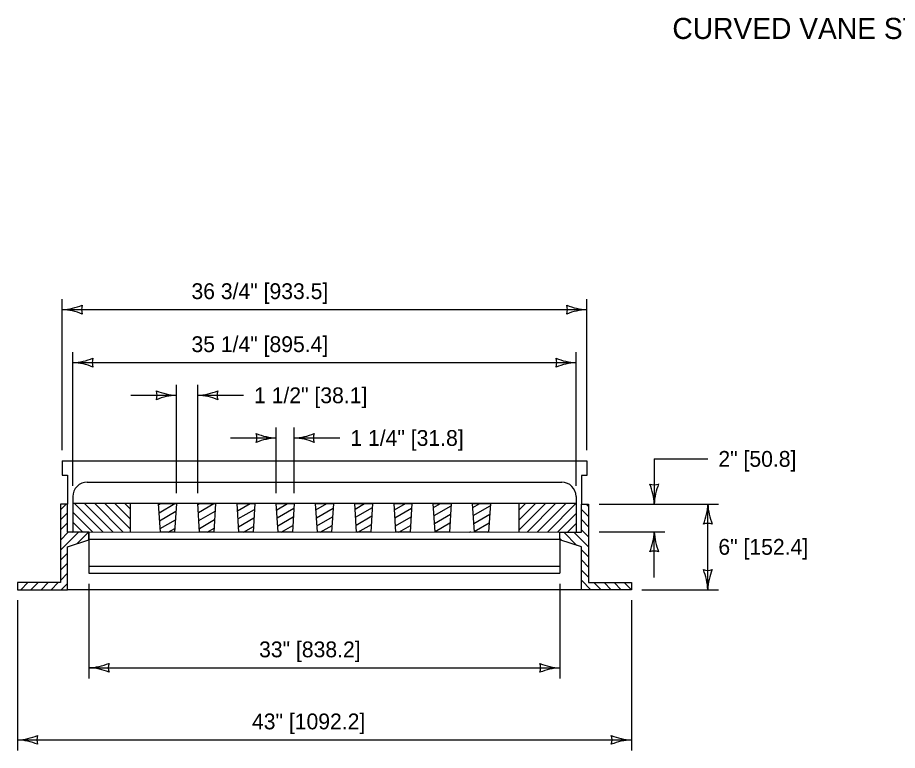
# Model space of a CAD drawing. Extents: x 49991.4 to 50057, y 49987.6 to 50011.4.
# Drawn here: x 50008.587 to 50011.925, y 49993.335 to 49996.116 of the extents above; entities that cross this region are included whole.
import ezdxf

# ---------------------------------------------------------------- set-up
doc = ezdxf.new("R2010")
doc.units = 0
for name, color, linetype in [('Level 1', 7, 'Continuous'), ('Level 2', 7, 'Continuous'), ('Level 3', 7, 'Continuous')]:
    doc.layers.add(name, color=color, linetype=linetype)

msp = doc.modelspace()

# ---------------------------------------------------------------- linework, layer by layer
at = {"layer": 'Level 1'}
for p, q in [((50008.7559, 49994.434), (50008.7559, 49994.3799)), ((50008.7559, 49994.434), (50010.7465, 49994.434)), ((50010.7465, 49994.434), (50010.7465, 49994.3782)), ((50008.7559, 49994.3799), (50008.7762, 49994.3798)), ((50008.7762, 49994.3798), (50008.7762, 49994.2698)), ((50010.7262, 49994.3782), (50010.7262, 49994.2698)), ((50010.7465, 49994.3782), (50010.7262, 49994.3782)), ((50008.8507, 49994.3527), (50010.6518, 49994.3527)), ((50008.7491, 49994.2482), (50008.7707, 49994.2698)), ((50008.7965, 49994.2985), (50008.7965, 49994.2714)), ((50010.7059, 49994.2714), (50008.7965, 49994.2714)), ((50008.7965, 49994.2714), (50008.7965, 49994.163)), ((50008.8025, 49994.2714), (50008.9109, 49994.163)), ((50008.8408, 49994.2714), (50008.9492, 49994.163)), ((50008.8791, 49994.2714), (50008.9875, 49994.163)), ((50008.9174, 49994.2714), (50009.0132, 49994.1757)), ((50008.9557, 49994.2714), (50009.0132, 49994.214)), ((50008.994, 49994.2714), (50009.0132, 49994.2523)), ((50009.0132, 49994.2714), (50009.0132, 49994.163)), ((50009.1218, 49994.2671), (50009.1293, 49994.2714)), ((50009.1237, 49994.2369), (50009.1834, 49994.2714)), ((50009.2707, 49994.2678), (50009.2769, 49994.2714)), ((50009.2726, 49994.2377), (50009.3311, 49994.2714)), ((50009.4212, 49994.2437), (50009.4692, 49994.2714)), ((50009.5699, 49994.2475), (50009.6114, 49994.2714)), ((50009.7188, 49994.2475), (50009.7604, 49994.2714)), ((50009.8676, 49994.2507), (50009.9035, 49994.2714)), ((50010.0167, 49994.2475), (50010.0583, 49994.2714)), ((50010.1652, 49994.2562), (50010.1915, 49994.2714)), ((50010.3141, 49994.2562), (50010.3405, 49994.2714)), ((50010.4892, 49994.2714), (50010.4892, 49994.1646)), ((50010.4892, 49994.1705), (50010.5902, 49994.2714)), ((50010.4892, 49994.2088), (50010.5519, 49994.2714)), ((50010.4892, 49994.2471), (50010.5136, 49994.2714)), ((50010.5217, 49994.1646), (50010.6285, 49994.2714)), ((50010.56, 49994.1646), (50010.6668, 49994.2714)), ((50010.5983, 49994.1646), (50010.7051, 49994.2714)), ((50010.7059, 49994.2985), (50010.7059, 49994.2714)), ((50010.7059, 49994.2714), (50010.7059, 49994.1646)), ((50010.7439, 49994.2698), (50010.7533, 49994.2604)), ((50008.7491, 49994.2099), (50008.7762, 49994.237)), ((50008.7965, 49994.2391), (50008.8726, 49994.163)), ((50009.1255, 49994.2067), (50009.1874, 49994.2425)), ((50009.2745, 49994.2075), (50009.3364, 49994.2432)), ((50009.423, 49994.2135), (50009.4858, 49994.2497)), ((50009.5718, 49994.2173), (50009.635, 49994.2538)), ((50009.7207, 49994.2173), (50009.7839, 49994.2538)), ((50009.8695, 49994.2205), (50009.9331, 49994.2573)), ((50010.0186, 49994.2173), (50010.0819, 49994.2538)), ((50010.167, 49994.226), (50010.2314, 49994.2632)), ((50010.316, 49994.226), (50010.3804, 49994.2632)), ((50010.7262, 49994.2492), (50010.7533, 49994.2221)), ((50009.1274, 49994.1766), (50009.1854, 49994.21)), ((50009.2763, 49994.1773), (50009.3344, 49994.2108)), ((50009.4249, 49994.1833), (50009.4837, 49994.2173)), ((50009.5736, 49994.1871), (50009.633, 49994.2213)), ((50009.7226, 49994.1871), (50009.7819, 49994.2213)), ((50009.8714, 49994.1903), (50009.9311, 49994.2248)), ((50010.0205, 49994.1871), (50010.0798, 49994.2213)), ((50010.1689, 49994.1959), (50010.2294, 49994.2308)), ((50010.3179, 49994.1959), (50010.3783, 49994.2308)), ((50010.6366, 49994.1646), (50010.7059, 49994.2339)), ((50010.7262, 49994.2109), (50010.7533, 49994.1838)), ((50008.7491, 49994.1716), (50008.7762, 49994.1987)), ((50008.7965, 49994.2008), (50008.8343, 49994.163)), ((50009.1583, 49994.1631), (50009.1833, 49994.1776)), ((50009.3059, 49994.1631), (50009.3323, 49994.1784)), ((50009.4441, 49994.1631), (50009.4817, 49994.1848)), ((50009.5863, 49994.1631), (50009.6309, 49994.1889)), ((50009.7352, 49994.1631), (50009.7799, 49994.1889)), ((50009.8784, 49994.1631), (50009.9291, 49994.1924)), ((50010.0331, 49994.1631), (50010.0778, 49994.1889)), ((50010.1708, 49994.1657), (50010.2273, 49994.1983)), ((50010.3198, 49994.1657), (50010.3763, 49994.1983)), ((50010.6749, 49994.1646), (50010.7059, 49994.1956)), ((50010.7262, 49994.1726), (50010.7533, 49994.1455)), ((50008.7491, 49994.095), (50008.8172, 49994.163)), ((50008.7491, 49994.1333), (50008.7789, 49994.163)), ((50008.7762, 49994.1658), (50008.7789, 49994.163)), ((50008.7965, 49994.163), (50010.7262, 49994.1646)), ((50008.8115, 49994.1191), (50008.8555, 49994.163)), ((50008.8574, 49994.163), (50008.8574, 49994.0073)), ((50008.8574, 49994.136), (50010.6449, 49994.136)), ((50010.3018, 49994.1631), (50010.3066, 49994.1659)), ((50010.3695, 49994.1631), (50010.3743, 49994.1659)), ((50010.6449, 49994.139), (50010.6518, 49994.1321)), ((50010.6449, 49994.136), (50010.6449, 49994.0073)), ((50010.6592, 49994.163), (50010.7092, 49994.113)), ((50010.6975, 49994.163), (50010.7533, 49994.1072)), ((50008.7491, 49994.0567), (50008.7762, 49994.0838)), ((50010.7262, 49994.096), (50010.7533, 49994.0689)), ((50008.7491, 49994.0184), (50008.7762, 49994.0455)), ((50010.7262, 49994.0577), (50010.7533, 49994.0306)), ((50008.7491, 49993.9801), (50008.7762, 49994.0072)), ((50008.8574, 49994.0344), (50010.6449, 49994.0344)), ((50008.8574, 49994.0073), (50010.6449, 49994.0073)), ((50010.7262, 49994.0194), (50010.7533, 49993.9923)), ((50008.5866, 49993.9708), (50008.5877, 49993.9719)), ((50008.5989, 49993.9448), (50008.626, 49993.9719)), ((50008.6372, 49993.9448), (50008.6643, 49993.9719)), ((50008.6755, 49993.9448), (50008.7026, 49993.9719)), ((50008.7138, 49993.9448), (50008.7409, 49993.9719)), ((50008.7521, 49993.9448), (50008.7762, 49993.9689)), ((50010.7262, 49993.9811), (50010.7625, 49993.9448)), ((50010.7737, 49993.9719), (50010.8008, 49993.9448)), ((50010.812, 49993.9719), (50010.8391, 49993.9448)), ((50010.8503, 49993.9719), (50010.8774, 49993.9448)), ((50010.8886, 49993.9719), (50010.9157, 49993.9448)), ((50010.7262, 49993.9448), (50008.7762, 49993.9448))]:
    msp.add_line(p, q, dxfattribs=at)
for points in [[(50008.7491, 49994.2698), (50008.7491, 49993.9719), (50008.5866, 49993.9719), (50008.5866, 49993.9448), (50008.7762, 49993.9448), (50008.7762, 49994.1073), (50008.8574, 49994.1344), (50008.8574, 49994.163), (50008.7762, 49994.163), (50008.7762, 49994.163), (50008.7762, 49994.2698)], [(50009.1283, 49994.1631), (50009.1215, 49994.2714), (50009.1892, 49994.2714), (50009.1824, 49994.1631)], [(50009.2772, 49994.1631), (50009.2705, 49994.2714), (50009.3382, 49994.2714), (50009.3314, 49994.1631)], [(50009.4262, 49994.1631), (50009.4194, 49994.2714), (50009.4871, 49994.2714), (50009.4804, 49994.1631)], [(50009.5751, 49994.1631), (50009.5684, 49994.2714), (50009.6361, 49994.2714), (50009.6293, 49994.1631)], [(50009.7241, 49994.1631), (50009.7173, 49994.2714), (50009.785, 49994.2714), (50009.7783, 49994.1631)], [(50009.8731, 49994.1631), (50009.8663, 49994.2714), (50009.934, 49994.2714), (50009.9272, 49994.1631)], [(50010.022, 49994.1631), (50010.0152, 49994.2714), (50010.083, 49994.2714), (50010.0762, 49994.1631)], [(50010.171, 49994.1631), (50010.1642, 49994.2714), (50010.2319, 49994.2714), (50010.2251, 49994.1631)], [(50010.3199, 49994.1631), (50010.3132, 49994.2714), (50010.3809, 49994.2714), (50010.3741, 49994.1631)], [(50010.7533, 49994.2698), (50010.7533, 49993.9719), (50010.9158, 49993.9719), (50010.9158, 49993.9448), (50010.7262, 49993.9448), (50010.7262, 49994.1073), (50010.6449, 49994.1344), (50010.6449, 49994.163), (50010.7262, 49994.163), (50010.7262, 49994.2698)]]:
    msp.add_lwpolyline(points, close=True, dxfattribs=at)
for centre, start, end in [((50008.8507, 49994.2985), 89.9504, 180), ((50010.6517, 49994.2985), 0, 89.9504)]:
    msp.add_arc(centre, 0.0542, start, end, dxfattribs=at)
at = {"layer": 'Level 3'}
for p, q in [((50008.7559, 49994.474), (50008.7559, 49995.0477)), ((50010.7465, 49994.474), (50010.7465, 49995.0477)), ((50008.7559, 49995.0077), (50010.7465, 49995.0077)), ((50008.7965, 49994.3385), (50008.7965, 49994.8465)), ((50010.7059, 49994.3385), (50010.7059, 49994.8465)), ((50008.7965, 49994.8065), (50010.7059, 49994.8065)), ((50009.1892, 49994.3114), (50009.1892, 49994.7226)), ((50009.2705, 49994.3114), (50009.2705, 49994.7226)), ((50009.0158, 49994.6826), (50009.1892, 49994.6826)), ((50009.2705, 49994.6826), (50009.4439, 49994.6826)), ((50009.5684, 49994.3114), (50009.5684, 49994.5606)), ((50009.6361, 49994.3114), (50009.6361, 49994.5606)), ((50009.3949, 49994.5206), (50009.5684, 49994.5206)), ((50009.6361, 49994.5206), (50009.8095, 49994.5206)), ((50011.0025, 49994.4412), (50011.0025, 49994.2698)), ((50011.0025, 49994.4412), (50011.206, 49994.4412)), ((50010.7933, 49994.2698), (50011.246, 49994.2698)), ((50011.206, 49993.9448), (50011.206, 49994.2698)), ((50010.7933, 49994.1646), (50011.0425, 49994.1646)), ((50011.0025, 49993.9912), (50011.0025, 49994.1646)), ((50008.8574, 49993.9673), (50008.8574, 49993.6082)), ((50010.6449, 49993.9673), (50010.6449, 49993.6082)), ((50010.9558, 49993.9448), (50011.246, 49993.9448)), ((50008.5866, 49993.9048), (50008.5866, 49993.3348)), ((50010.9158, 49993.9048), (50010.9158, 49993.3348)), ((50008.8574, 49993.6482), (50010.6449, 49993.6482)), ((50008.5866, 49993.3748), (50010.9158, 49993.3748))]:
    msp.add_line(p, q, dxfattribs=at)
for centre, radius, start, end in [((50008.7444, 49995.2404), 0.233, 272.8273, 292.0772), ((50008.7468, 49994.7856), 0.2223, 67.456, 87.6395), ((50008.8841, 49995.0077), 0.0548, 162.1388, 197.8612), ((50010.7557, 49995.2298), 0.2223, 247.456, 267.6395), ((50010.6183, 49995.0077), 0.0548, 342.1388, 17.8612), ((50010.758, 49994.775), 0.233, 92.8273, 112.0772), ((50008.785, 49995.0392), 0.233, 272.8273, 292.0772), ((50008.7873, 49994.5844), 0.2223, 67.456, 87.6395), ((50008.9247, 49994.8065), 0.0548, 162.1388, 197.8612), ((50010.715, 49995.0286), 0.2223, 247.456, 267.6395), ((50010.5777, 49994.8065), 0.0548, 342.1388, 17.8612), ((50010.7174, 49994.5738), 0.233, 92.8273, 112.0772), ((50009.1984, 49994.9048), 0.2223, 247.456, 267.6395), ((50009.061, 49994.6826), 0.0548, 342.1388, 17.8612), ((50009.2007, 49994.4499), 0.233, 92.8273, 112.0772), ((50009.259, 49994.9153), 0.233, 272.8273, 292.0772), ((50009.259, 49994.9153), 0.233, 272.8273, 292.0772), ((50009.2613, 49994.4605), 0.2223, 67.456, 87.6395), ((50009.2613, 49994.4605), 0.2223, 67.456, 87.6395), ((50009.3987, 49994.6826), 0.0548, 162.1388, 197.8612), ((50009.3987, 49994.6826), 0.0548, 162.1388, 197.8612), ((50009.5775, 49994.7427), 0.2223, 247.456, 267.6395), ((50009.4402, 49994.5206), 0.0548, 342.1388, 17.8612), ((50009.6246, 49994.7533), 0.233, 272.8273, 292.0772), ((50009.6246, 49994.7533), 0.233, 272.8273, 292.0772), ((50009.7643, 49994.5206), 0.0548, 162.1388, 197.8612), ((50009.7643, 49994.5206), 0.0548, 162.1388, 197.8612), ((50009.5799, 49994.2879), 0.233, 92.8273, 112.0772), ((50009.6269, 49994.2985), 0.2223, 67.456, 87.6395), ((50009.6269, 49994.2985), 0.2223, 67.456, 87.6395), ((50011.0025, 49994.398), 0.0548, 252.1388, 287.8612), ((50010.7698, 49994.2583), 0.233, 2.8273, 22.0772), ((50011.2246, 49994.2607), 0.2223, 157.456, 177.6395), ((50010.9839, 49994.279), 0.2223, 337.456, 357.6395), ((50011.4387, 49994.2813), 0.233, 182.8273, 202.0772), ((50011.206, 49994.1416), 0.0548, 72.1388, 107.8612), ((50010.7804, 49994.1738), 0.2223, 337.456, 357.6395), ((50011.2352, 49994.1761), 0.233, 182.8273, 202.0772), ((50011.0025, 49994.0364), 0.0548, 72.1388, 107.8612), ((50011.206, 49994.073), 0.0548, 252.1388, 287.8612), ((50010.9733, 49993.9333), 0.233, 2.8273, 22.0772), ((50011.4281, 49993.9357), 0.2223, 157.456, 177.6395), ((50008.8459, 49993.8809), 0.233, 272.8273, 292.0772), ((50008.8483, 49993.4261), 0.2223, 67.456, 87.6395), ((50008.9857, 49993.6482), 0.0548, 162.1388, 197.8612), ((50010.6541, 49993.8703), 0.2223, 247.456, 267.6395), ((50010.5167, 49993.6482), 0.0548, 342.1388, 17.8612), ((50010.6564, 49993.4155), 0.233, 92.8273, 112.0772), ((50008.5751, 49993.6075), 0.233, 272.8273, 292.0772), ((50008.5774, 49993.1527), 0.2223, 67.456, 87.6395), ((50008.7148, 49993.3748), 0.0548, 162.1388, 197.8612), ((50010.9249, 49993.5969), 0.2223, 247.456, 267.6395), ((50010.7876, 49993.3748), 0.0548, 342.1388, 17.8612), ((50010.9273, 49993.1421), 0.233, 92.8273, 112.0772)]:
    msp.add_arc(centre, radius, start, end, dxfattribs=at)

# ---------------------------------------------------------------- texts
at = {"layer": 'Level 2'}
for s, height, p in [('CURVED VANE STYLE *', 0.08, (50011.0714, 49996.0349)), ('36 3/4" [933.5]', 0.06, (50009.2464, 49995.0477)), ('35 1/4" [895.4]', 0.06, (50009.2464, 49994.8465)), ('1 1/2" [38.1]', 0.06, (50009.4839, 49994.6526)), ('1 1/4" [31.8]', 0.06, (50009.8495, 49994.4906)), ('2" [50.8]', 0.06, (50011.246, 49994.4112)), ('6" [152.4]', 0.06, (50011.246, 49994.0773)), ('33" [838.2]', 0.06, (50009.503, 49993.6882)), ('43" [1092.2]', 0.06, (50009.4761, 49993.4148))]:
    msp.add_text(s, height=height, dxfattribs=at).set_placement(p)

doc.saveas('drawing.dxf')
